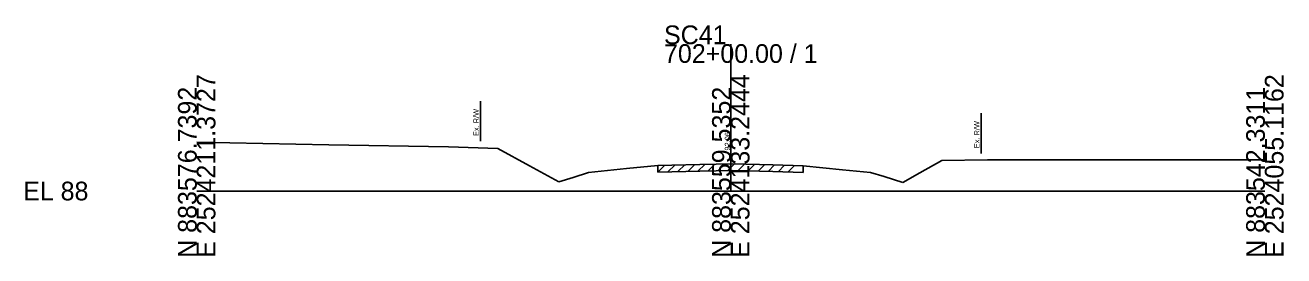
# Model space of a CAD drawing. Extents: x -26 to 183, y -10 to 24021.
# Drawn here: x -25.7 to 162.8, y 22990.3 to 23024.8 of the extents above; entities that cross this region are included whole.
import ezdxf

# ---------------------------------------------------------------- set-up
doc = ezdxf.new("R2010")
doc.units = 0
for name, color, linetype in [('RD_GPK_XS_Cell', 7, 'Continuous'), ('RD_XS_ExGround', 7, 'Continuous'), ('RD_XS_ExPaveRet', 7, 'Continuous'), ('RD_XS_ExRW', 7, 'Continuous'), ('RD_XS_TX_Elev_EX', 7, 'Continuous')]:
    doc.layers.add(name, color=color, linetype=linetype)

msp = doc.modelspace()

# ---------------------------------------------------------------- linework, layer by layer
at = {"layer": 'RD_GPK_XS_Cell'}
for p, q in [((80, 23000), (80, 23021.98)), ((0, 23000), (80, 23000)), ((80, 23000), (160, 23000))]:
    msp.add_line(p, q, dxfattribs=at)
at = {"layer": 'RD_XS_ExGround'}
for p, q in [((0, 23007.33), (19.77, 23006.92)), ((19.77, 23006.92), (37.73, 23006.6)), ((37.73, 23006.6), (45.1, 23006.38)), ((45.1, 23006.38), (49.84, 23003.77)), ((49.84, 23003.77), (54.22, 23001.38)), ((58.7, 23002.78), (64.37, 23003.37)), ((64.37, 23003.37), (69.08, 23003.84)), ((69.08, 23003.84), (75.36, 23003.96)), ((75.36, 23003.96), (80.26, 23004.07)), ((80.26, 23004.07), (86.32, 23003.91)), ((86.32, 23003.91), (90.86, 23003.79)), ((90.86, 23003.79), (96.71, 23003.19)), ((96.71, 23003.19), (100.94, 23002.77)), ((108.34, 23002.74), (111.59, 23004.59)), ((111.59, 23004.59), (118.45, 23004.65)), ((118.45, 23004.65), (132.34, 23004.65)), ((132.34, 23004.65), (160, 23004.65)), ((54.22, 23001.38), (56.38, 23002.01)), ((56.38, 23002.01), (58.7, 23002.78)), ((100.94, 23002.77), (102.98, 23002.16)), ((102.98, 23002.16), (105.79, 23001.28)), ((105.79, 23001.28), (108.34, 23002.74))]:
    msp.add_line(p, q, dxfattribs=at)
at = {"layer": 'RD_XS_ExPaveRet'}
for p, q in [((69.08, 23002.84), (70.1, 23003.86)), ((69.08, 23002.84), (69.08, 23003.84)), ((69.08, 23002.84), (75.36, 23002.96)), ((70.58, 23002.87), (71.6, 23003.89)), ((72.08, 23002.9), (73.1, 23003.92)), ((73.58, 23002.93), (74.6, 23003.95)), ((75.08, 23002.96), (76.1, 23003.98)), ((75.36, 23002.96), (80.26, 23003.07)), ((76.58, 23002.99), (77.6, 23004.01)), ((78.08, 23003.02), (79.1, 23004.04)), ((79.58, 23003.05), (80.58, 23004.06)), ((80.26, 23003.07), (86.32, 23002.91)), ((81.08, 23003.04), (82.05, 23004.02)), ((82.58, 23003.01), (83.55, 23003.98)), ((84.08, 23002.97), (85.05, 23003.94)), ((85.58, 23002.93), (86.55, 23003.9)), ((86.32, 23002.91), (90.86, 23002.79)), ((87.08, 23002.89), (88.05, 23003.86)), ((88.58, 23002.85), (89.55, 23003.82)), ((90.86, 23003.79), (90.86, 23002.79))]:
    msp.add_line(p, q, dxfattribs=at)
at = {"layer": 'RD_XS_ExRW'}
for p, q in [((42.5, 23013.46), (42.5, 23007.46)), ((117.5, 23011.64), (117.5, 23005.64))]:
    msp.add_line(p, q, dxfattribs=at)

# ---------------------------------------------------------------- texts
at = {"layer": 'RD_GPK_XS_Cell'}
for s, p in [('SC41', (70, 23021.98)), ('702+00.00 / 1', (70, 23019.18)), ('EL 88', (-26, 22998.6))]:
    msp.add_text(s, height=2.8, dxfattribs=at).set_placement(p)
for s, p in [('E 2524211.3727', (2.8, 22990)), ('E 2524133.2444', (82.8, 22990)), ('E 2524055.1162', (162.8, 22990)), ('N 883576.7392', (0, 22990)), ('N 883559.5352', (80, 22990)), ('N 883542.3311', (160, 22990))]:
    msp.add_text(s, height=2.8, rotation=90, dxfattribs=at).set_placement(p)
at = {"layer": 'RD_XS_ExRW'}
for p in [(42.25, 23008.24), (117.25, 23006.42)]:
    msp.add_text('Ex. R/W ', height=0.8, rotation=90, dxfattribs=at).set_placement(p)
at = {"layer": 'RD_XS_TX_Elev_EX'}
msp.add_text('92.06', height=0.8, rotation=90, dxfattribs=at).set_placement((79.9, 23006.06))

doc.saveas('drawing.dxf')
